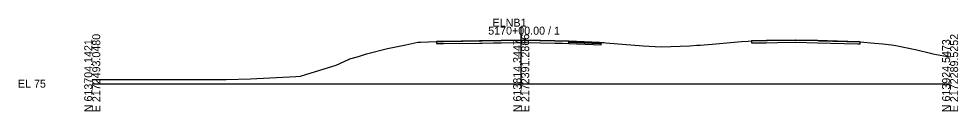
# Model space of a CAD drawing. Extents: x -26 to 1303, y -3010 to 12038.
# Drawn here: x -25.7 to 302.8, y -1009.7 to -977.2 of the extents above; entities that cross this region are included whole.
import ezdxf

# ---------------------------------------------------------------- set-up
doc = ezdxf.new("R2010")
doc.units = 0
for name, color, linetype in [('RD_GPK_XS_Cell', 7, 'Continuous'), ('RD_XS_Base', 7, 'Continuous'), ('RD_XS_ExGround', 7, 'Continuous'), ('RD_XS_ExPaveRet', 7, 'Continuous'), ('RD_XS_Pave', 7, 'Continuous'), ('RD_XS_PaveOvlay_CP', 7, 'Continuous')]:
    doc.layers.add(name, color=color, linetype=linetype)

msp = doc.modelspace()

# ---------------------------------------------------------------- linework, layer by layer
at = {"layer": 'RD_GPK_XS_Cell'}
for p, q in [((150, -1000), (150, -980)), ((0, -1000), (150, -1000)), ((150, -1000), (300, -1000))]:
    msp.add_line(p, q, dxfattribs=at)
at = {"layer": 'RD_XS_Base'}
for p, q in [((177.44, -985.87), (166.7, -985.44)), ((166.7, -985.87), (166.7, -985.94)), ((166.7, -985.94), (177.94, -986.39)), ((177.94, -985.89), (177.44, -985.87)), ((177.44, -985.87), (177.44, -985.87)), ((177.94, -986.39), (177.94, -985.89)), ((177.94, -985.89), (177.94, -985.89))]:
    msp.add_line(p, q, dxfattribs=at)
at = {"layer": 'RD_XS_ExGround'}
msp.add_lwpolyline([(0, -998.59), (46.02, -998.59), (46.86, -998.56), (55.38, -998.36), (71.17, -997.48), (72.86, -997.41), (75.07, -996.71), (85.25, -993.49), (89.61, -991.56), (89.99, -991.3), (90.56, -991.22), (93.16, -990.41), (95.87, -989.49), (103.24, -987.64), (103.81, -987.5), (109.68, -986.31), (113.84, -985.44), (114.75, -985.41), (120.36, -985.19), (122.87, -985.17), (136.39, -984.99), (143.01, -984.88), (151.07, -984.75), (161.75, -985.01), (166.7, -985.12), (168.66, -985.31), (169.54, -985.35), (176.8, -985.51), (178.94, -985.55), (179.61, -985.62), (192.62, -986.67), (198.94, -987.1), (209.01, -986.66), (211.46, -986.54), (212.55, -986.5), (216.79, -986.13), (227.09, -985.19), (229.34, -985.05), (230.41, -984.98), (230.5, -984.97), (241.9, -984.76), (245.96, -984.69), (253.58, -984.9), (254.27, -984.92), (268.56, -985.32), (273.51, -985.84), (276.49, -986.06), (279.49, -986.36), (280.34, -986.45), (281.08, -986.58), (288.32, -988.08), (293.13, -989.25), (293.99, -989.49), (299.07, -990.44), (299.38, -990.5), (299.42, -990.5), (299.97, -990.58), (300, -990.59)], dxfattribs=at)
at = {"layer": 'RD_XS_ExPaveRet'}
for points in [[(161.75, -985.01), (151.73, -984.76), (151.07, -984.75), (150.57, -984.76), (143.01, -984.88), (140.34, -984.93), (136.39, -984.99), (135.47, -985), (122.87, -985.17), (120.36, -985.19), (120.36, -985.36), (120.36, -985.94), (122.87, -985.92), (135.47, -985.75), (136.39, -985.74), (140.34, -985.68), (143.01, -985.63), (150.57, -985.51), (151.07, -985.5), (151.73, -985.51), (161.75, -985.76), (164.49, -985.82), (166.7, -985.87), (166.7, -985.29), (166.7, -985.12), (164.49, -985.07), (161.75, -985.01)], [(161.75, -985.01), (151.73, -984.76), (151.07, -984.75), (150.57, -984.76), (143.01, -984.88), (140.34, -984.93), (136.39, -984.99), (135.47, -985), (122.87, -985.17), (120.36, -985.19), (120.36, -985.36), (120.36, -985.94), (122.87, -985.92), (135.47, -985.75), (136.39, -985.74), (140.34, -985.68), (143.01, -985.63), (150.57, -985.51), (151.07, -985.5), (151.73, -985.51), (161.75, -985.76), (164.49, -985.82), (166.7, -985.87), (166.7, -985.29), (166.7, -985.12), (164.49, -985.07), (161.75, -985.01)], [(267.79, -985.3), (253.59, -984.9), (246, -984.69), (246, -984.69), (245.96, -984.69), (245.94, -984.69), (245.89, -984.69), (239.69, -984.81), (235.65, -984.88), (232.2, -984.94), (230.5, -984.97), (230.5, -985.25), (230.5, -985.72), (232.2, -985.69), (235.65, -985.63), (239.69, -985.56), (245.89, -985.44), (245.94, -985.44), (245.96, -985.44), (246, -985.44), (246, -985.44), (253.59, -985.65), (267.79, -986.05), (268.48, -986.07), (268.56, -986.07), (268.56, -985.6), (268.56, -985.32), (268.48, -985.32), (267.79, -985.3)], [(267.79, -985.3), (253.59, -984.9), (246, -984.69), (246, -984.69), (245.96, -984.69), (245.94, -984.69), (245.89, -984.69), (239.69, -984.81), (235.65, -984.88), (232.2, -984.94), (230.5, -984.97), (230.5, -985.25), (230.5, -985.72), (232.2, -985.69), (235.65, -985.63), (239.69, -985.56), (245.89, -985.44), (245.94, -985.44), (245.96, -985.44), (246, -985.44), (246, -985.44), (253.59, -985.65), (267.79, -986.05), (268.48, -986.07), (268.56, -986.07), (268.56, -985.6), (268.56, -985.32), (268.48, -985.32), (267.79, -985.3)]]:
    msp.add_lwpolyline(points, dxfattribs=at)
at = {"layer": 'RD_XS_Pave'}
for p, q in [((177.44, -985.55), (166.7, -985.12)), ((177.44, -985.71), (166.7, -985.28)), ((166.7, -985.28), (177.44, -985.71)), ((166.7, -985.44), (177.44, -985.87)), ((177.44, -985.71), (177.44, -985.55)), ((177.44, -985.55), (177.44, -985.55)), ((177.44, -985.87), (177.44, -985.71)), ((177.44, -985.71), (177.44, -985.71))]:
    msp.add_line(p, q, dxfattribs=at)
at = {"layer": 'RD_XS_PaveOvlay_CP'}
msp.add_line((177.44, -985.55), (166.7, -985.12), dxfattribs=at)

# ---------------------------------------------------------------- texts
at = {"layer": 'RD_GPK_XS_Cell'}
for s, p in [('ELNB1', (140, -980)), ('5170+00.00 / 1', (138.46, -982.8)), ('EL 75', (-26, -1001.4))]:
    msp.add_text(s, height=2.8, dxfattribs=at).set_placement(p)
for s, p in [('N 613704.1421', (0, -1010)), ('E 2172493.0480', (2.8, -1010)), ('N 613814.3447', (150, -1010)), ('E 2172391.2866', (152.8, -1010)), ('N 613924.5473', (300, -1010)), ('E 2172289.5252', (302.8, -1010))]:
    msp.add_text(s, height=2.8, rotation=90, dxfattribs=at).set_placement(p)

doc.saveas('drawing.dxf')
